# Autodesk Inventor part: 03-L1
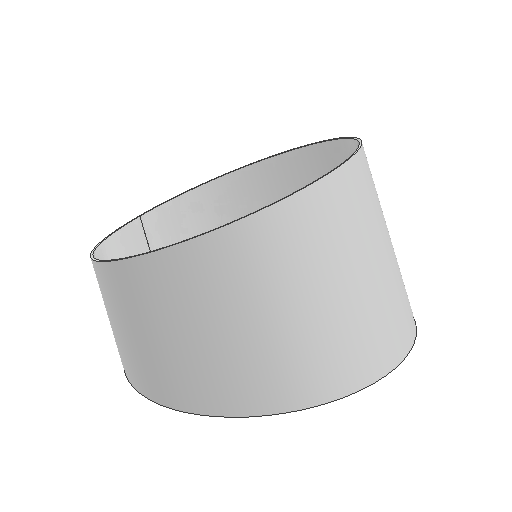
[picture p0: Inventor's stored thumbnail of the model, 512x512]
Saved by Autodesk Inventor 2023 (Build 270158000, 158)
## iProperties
Created: 2023-01
Part Number: 03-L1
Material: Generic
Document SubType Name: Sheet Metal
Designer: Nelson C Agudelo A
Density: 1 g/cm^3
Sheet Metal Rule: Default_mm
Appearance: Default
Flat Pattern Width: 20.5874 cm
Flat Pattern Length: 84.8759 cm
Flat Pattern Area: 1747.38 cm^2
Sheet Metal Width: 205,874 mm
Sheet Metal Length: 848,759 mm
Sheet Metal Area: 174737,739 mm^2
Author: Nelson C Agudelo A
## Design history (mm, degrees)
derived "01-Esquema Codo Mitrado.ipt"
  sketch "Sketch1"
    geometry: L1 (0, 0)-(381, 0) reference; L2 (381, 0)-(381, 75.786) reference; L3 (244.5, 0)-(244.5, 48.634) reference; L4 (517.5, 0)-(517.5, 102.937) reference; L5 (0, 0)-(517.5, 102.937) reference; L6 (0, 0)-(0, 381) reference; L7 (0, 244.5)-(48.634, 244.5) reference; L8 (0, 517.5)-(102.937, 517.5) reference; L9 (0, 381)-(0, 517.5) reference; L10 (0, 0)-(102.937, 517.5) reference; L11 (0, 381)-(75.786, 381) reference; L12 (0, 0)-(322.996, 215.819) reference; L13 (381, 75.786)-(322.996, 215.819) reference; L14 (0, 0)-(351.998, 145.802) reference; L15 (517.5, 0)-(898.5, 0) reference; L16 (381, 0)-(762, 0) reference; L17 (762, 0)-(1143, 0) reference; 1 further point
workplane "Work Plane1"
node "Contour Flange1"
  sketch "Sketch2"
    geometry: L1 (136.5, 0.05)-(136.5, -0.05); A1 r 136.5 centre (0, 0) between (136.5, 0.05) and (136.5, -0.05); 3 further points
    constraints: 2 end point, 2 point on circle, 1 centre point, 1 coincident, 1 midpoint, 1 vertical
    dimensions: "d22" = 136.5 radius of A1 (= 0.5 x ODtuberia); "d23" = 0.1 distance of L1.start L1.end
sketch "Sketch3"
  geometry: L1 (517.5, 102.937)-(265.281, -1.535) reference; L2 (0, 0)-(517.5, 102.937); L3 (0, 0)-(394.731, 399.327); L4 (438.715, 293.14)-(186.496, 188.668) reference; L5 (394.731, 399.327)-(438.715, 293.14); L6 (0, 0)-(561.484, -3.25); L7 (561.484, -3.25)-(517.5, 102.937); L8 (0, 0)-(438.715, 293.14)
  constraints: 12 end point, 2 point on line, 1 collinear, 1 perpendicular
cut "Cut1" sketch "Sketch3" dims "d24" = 2.5 (= Thickness), "d25" = 0
body "Solid1"
face "Plate1" dims "d7" = 2.5 (= Thickness), "d10" = 2.5 (= BendReliefWidth), "d11" = 1.25 (= BendReliefDepth), "d12" = 5 (= MinimumRemnant), "d15" = 2.5 (= TransitionRadius), "d16" = 205.8743 (= L1 + 2 x Recorte), "d17" = 2.5 (= BendRadius), "d18" = 0.5, "d19" = 10 (= CornerReliefSize), "d20" = 2.5 (= GapSize), "d21" = 2.5 (= JacobiRadiusSize), "SeamGap" = 0.01
bend "Bend1" dims "d7" = 2.5 (= Thickness), "d10" = 2.5 (= BendReliefWidth), "d11" = 1.25 (= BendReliefDepth), "d12" = 5 (= MinimumRemnant), "d15" = 2.5 (= TransitionRadius), "d17" = 2.5 (= BendRadius), "d18" = 0.5, "SeamGap" = 0.01
feature "Corner1" dims "d18" = 0.5, "d19" = 10 (= CornerReliefSize), "d20" = 2.5 (= GapSize), "d21" = 2.5 (= JacobiRadiusSize)
feature "Definition1"
other parameters: "Thickness" = 2.5 (derived), "BendRadius" = 2.5 (= Thickness), "BendReliefWidth" = 2.5 (= Thickness), "BendReliefDepth" = 1.25 (= 0.5 x Thickness), "MinimumRemnant" = 5 (= 2 x Thickness), "TransitionRadius" = 2.5 (= BendRadius), "JacobiRadiusSize" = 2.5 (= BendRadius), "GapSize" = 2.5 (= Thickness), "d1" = 381, "d2" = 75.78561, "d3" = 90 deg, "d4" = 273, "d5" = 136.5, "d6" = 273, "d8" = 273, "d9" = 136.5, "DL1" = 22.5 deg, "d13" = 151.57122, "L2" = 75.78561, "L1" = 151.57122, "Recorte" = 27.15154, "D" = 90 deg, "E1" = 381, "ODtuberia" = 273, "DL2" = 1.9635, "d14" = 27.15154, "BendRadius" = 2.5, "BendReliefDepth" = 1.25, "BendReliefWidth" = 2.5, "D" = 90 deg, "DL1" = 22.5 deg, "DL2" = 1.9635, "E1" = 381, "GapSize" = 2.5, "JacobiRadiusSize" = 2.5, "L1" = 151.57122, "L2" = 75.78561, "MinimumRemnant" = 5, "ODtuberia" = 273, "Recorte" = 27.15154, "Thickness" = 2.5, "TransitionRadius" = 2.5
